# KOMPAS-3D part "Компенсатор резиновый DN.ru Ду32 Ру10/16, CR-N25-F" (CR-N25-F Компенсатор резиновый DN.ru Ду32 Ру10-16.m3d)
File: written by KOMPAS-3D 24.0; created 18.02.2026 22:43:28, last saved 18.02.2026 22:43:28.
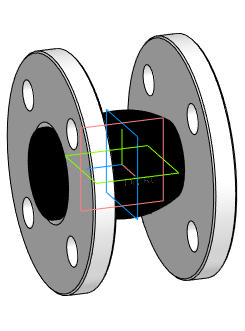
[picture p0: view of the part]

Document properties: Автор: DN.RU; Полное имя файла: D:\PROJECT CAD\DN.RU\...178(1)(ACTUALE). CR-N25-F Компенсатор резиновый DN.ru Ру10-16\DN32\CR-N25-F Компенсатор резиновый DN.ru Ду32 Ру10-16.m3d

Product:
- Body: Твердое тело2  | qty 1
    Масса: 3.844501
- Part/product: Компенсатор резиновый DN.ru Ду32 Ру10/16  | designation CR-N25-F
    Масса: 3
    Раздел спецификации: Прочие изделия
    Комментарий: D140-02389
    Примечание: D140-02389
    additional columns: Типовые

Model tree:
1. Твердое тело2  (labels: Твердое тело2)

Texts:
  CR-N25-F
